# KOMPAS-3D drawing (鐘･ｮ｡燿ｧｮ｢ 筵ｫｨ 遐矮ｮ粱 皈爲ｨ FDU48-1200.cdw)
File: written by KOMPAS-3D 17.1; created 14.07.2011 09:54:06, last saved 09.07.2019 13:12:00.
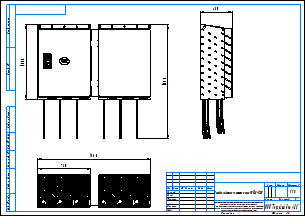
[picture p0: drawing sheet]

Title block, sheet 1: name: Преобразователи частоты серии FDU48-1200; scale: 1:10; sheets: 1; sheet format: A3; stored path: \\adlc.lan\data\АДЛ_ПКД\3D-модели\Поставщики\Оборудование Emotron\Преобразователи частоты\Серия FDU 2.0\KOMPAS 2D\Преобразователи частоты серии FDU48-1200.cdw

Views: Спереди 1
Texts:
  Рама для чертежей
  Лит-Масса-Масштаб
  Материал-Предприятие
  Масштаб
  Изм.
  Лист
  № докум.
  Подп.
  Дата
  Лит.
  Разраб.
  Пров.
  Т.контр.
  Листов
  Внимание! Данный продукт является объектом авторского права ООО «Торговый Дом АДЛ».
  Запрещается изменение, копирование, распространение
  (в том числе путем копирования на другие сайты и ресурсы в Интернете)
  или любое иное использование информации и объектов без предварительного
  согласия правообладателя (ООО «Торговый Дом АДЛ»).
  Н.контр.
  Утв.
  ООО "Торговый дом АДЛ"
  Изменение
  Номер документа
  Подпись
  Обозначение документа
  Наименование изделия
  Масса изделия по ГОСТ 2.109-73
  Порядковый номер листа
  Общее количество листов в документе
  Характер работы, выполненной лицом, подписавшим документ
  Наименование или индекс предприятия, выпускающего документ
  Инв. № подл.
  Подп. и дата
  Взам. инв. №
  Инв. № дубл.
  Инвентарный номер подлинника по ГОСТ 2.501-68
  Подпись принявшего подлинник в отдел технической документации
  Инвентарный номер подлинника, взамен которого выпущен данный подлинник
  Инвентарный номер дубликата по ГОСТ 2.502-68
  Подпись принявшего дубликат в отдел технической документации
  Справ. №
  Перв. примен.
  Обозначение документа, взамен или на основании которого выпущен данный документ
  Обозначение документа, в котором впервые записан данный документ
  Подпись лица, копировавшего чертеж
  Обозначение формата листа
  !Рама для чертежа
Dimensions and other numbers on the sheet: 1560; 730; 1036; 450; 1578; 1:10; 1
